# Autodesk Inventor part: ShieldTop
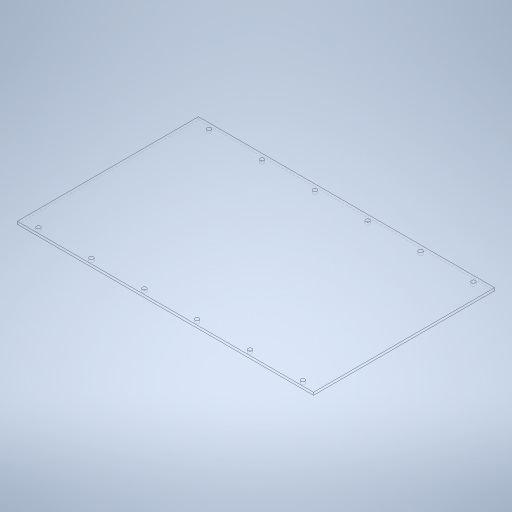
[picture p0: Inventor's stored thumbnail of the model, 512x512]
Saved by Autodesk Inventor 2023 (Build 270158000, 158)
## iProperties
Created: 2023-10
Part Number: ShieldTop
Material: Aluminum 7075
Document SubType Name: Modeling
Designer: tornqvih
Density: 2.81 g/cm^3
Appearance: Satin - Brushed Heavy
Author: tornqvih
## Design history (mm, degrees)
sketch "Sketch1"
  geometry: L1 (112, 68.5)-(-112, 68.5); L2 (-112, 68.5)-(-112, -68.5); L3 (-112, -68.5)-(112, -68.5); L4 (112, -68.5)-(112, 68.5); L5 (112, 68.5)-(-112, -68.5); L6 (-112, 68.5)-(112, -68.5); 1 further point
  constraints: 12 end point, 2 midpoint, 2 parallel, 1 horizontal, 1 perpendicular
  dimensions: "d0" = 137 distance of L3.end L1.start; "d1" = 224 distance of L1.start L1.end
extrude "Extrusion1" new body sketch "Sketch1" distance "d2" = 2; taper "d3" = 0 deg
sketch "Sketch2"
  geometry: L1 (112, 68.5)-(-112, 68.5) reference; L2 (-156.8, 0)-(156.8, 0) reference; L3 (-112, 68.5)-(-112, -68.5) reference; L4 (0, 95.9)-(0, -95.9) reference; 13 further points
  constraints: 9 symmetric about line, 2 horizontal alignment, 1 vertical alignment
  dimensions: "d4" = 4 distance from line of L1 point (-100, 64.5); "d13" = 20 distance from line of L4 point (-20, 64.5); "d14" = 60 distance from line of L4 point (-60, 64.5); "d15" = 100 distance from line of L4 point (-100, 64.5)
hole "Hole1" sketch "Sketch2" at (-100, 64.5), (-20, 64.5), (100, 64.5), (-100, -64.5), (-20, -64.5), (100, -64.5), (20, -64.5), (20, 64.5), (-60, -64.5), (-60, 64.5), (60, 64.5), (60, -64.5) diameter "d5" = 3; stored, may be unused: countersink angle "d9" = 90 deg, drill point angle "d11" = 118 deg; dims "d6" = 6, "d7" = 4, "d8" = 2, "d10" = 8
body "Solid1"
